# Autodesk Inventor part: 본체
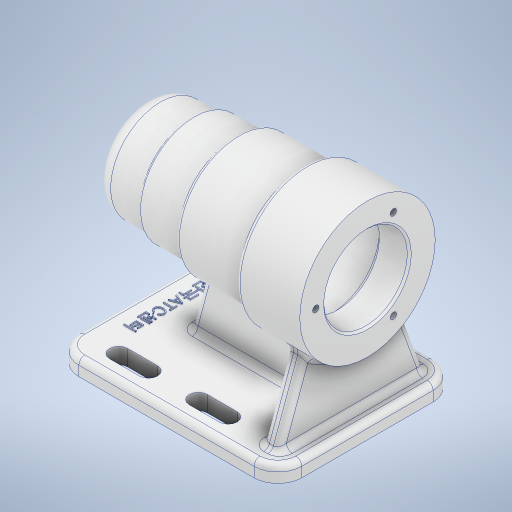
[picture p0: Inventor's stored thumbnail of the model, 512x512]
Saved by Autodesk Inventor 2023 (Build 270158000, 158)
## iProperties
Created: 2022-07
Part Number: 본체
Material: 알루미늄 6061
Document SubType Name: Modeling
Designer: owner
Density: 2.7 g/cm^3
Appearance: 알루미늄 - 평지
Author: owner
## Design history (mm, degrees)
sketch "스케치1"
  geometry: L1 (56, -45)-(-56, -45); L2 (-56, -45)-(-56, 45); L3 (-56, 45)-(56, 45); L4 (56, 45)-(56, -45); L5 (56, -45)-(-56, 45); L6 (-56, -45)-(56, 45); 1 further point
  constraints: 12 end point, 2 midpoint, 2 parallel, 1 horizontal, 1 perpendicular
  dimensions: "d0" = 112 distance of L1.start L1.end; "d1" = 90 distance of L1.end L2.end
extrude "돌출1" new body sketch "스케치1" distance "d2" = 8; taper "d3" = 0 deg
sketch "스케치2"
  geometry: L1 (-56, 70)-(56, 70); L2 (-56, 0)-(56, 0) reference; L3 (56, 0)-(56, 8) reference; L4 (-56, 70)-(-56, 87); L5 (-48, 95)-(-33, 95); L6 (-32, 96)-(-32, 96); L7 (-31, 97)-(-11.5, 97); L8 (-10, 98.5)-(-10, 98.5); L9 (-8.5, 100)-(22, 100); L10 (24, 102)-(24, 102); L11 (26, 104)-(56, 104); L12 (56, 104)-(56, 91); L13 (56, 91)-(41, 91); L14 (41, 91)-(41, 91); L15 (38, 94)-(-10, 94); L16 (-13, 91)-(-13, 91); L17 (-13, 91)-(-24.7, 91); L18 (-25, 90.7)-(-25, 87.5); L19 (-25, 87.5)-(-42.7, 87.5); L20 (-43, 87.2)-(-43, 86); L21 (-43, 86)-(-46.7, 86); L22 (-47, 85.7)-(-47, 80.5); L23 (-47, 80.5)-(-47, 80.5); L24 (-50, 77.5)-(-50, 70); A1 r 0.3 centre (-46.7, 85.7) between (-46.7, 86) and (-47, 85.7); A2 r 0.3 centre (-42.7, 87.2) between (-42.7, 87.5) and (-43, 87.2); A3 r 0.3 centre (-24.7, 90.7) between (-24.7, 91) and (-25, 90.7); A4 r 3 centre (-47, 77.5) between (-47, 80.5) and (-50, 77.5); A5 r 3 centre (-10, 91) between (-10, 94) and (-13, 91); A6 r 3 centre (38, 91) between (41, 91) and (38, 94); A7 r 8 centre (-48, 87) between (-48, 95) and (-56, 87); A8 r 1 centre (-31, 96) between (-31, 97) and (-32, 96); A9 r 1 centre (-33, 96) between (-33, 95) and (-32, 96); A10 r 1.5 centre (-8.5, 98.5) between (-8.5, 100) and (-10, 98.5); A11 r 1.5 centre (-11.5, 98.5) between (-11.5, 97) and (-10, 98.5); A12 r 2 centre (26, 102) between (26, 104) and (24, 102); A13 r 2 centre (22, 102) between (22, 100) and (24, 102); 12 further points
  constraints: 44 end point, 26 point on circle, 26 tangent, 20 perpendicular, 13 centre point, 10 point on line, 7 equal radius, 1 horizontal, 1 midpoint, 1 vertical
  dimensions: "d4" = 70 distance from line of point (0, 0) L1; "d5" = 112 distance of L1.start L1.end; "d6" = 21 diameter of L23 L1; "d7" = 50 diameter of L5 L1; "d8" = 32 diameter of L21 L1; "d9" = 35 diameter of L19 L1; "d10" = 42 diameter of L17 L1; "d11" = 48 diameter of L15 L1; "d12" = 42 diameter of L13 L1; "d13" = 54 diameter of L7 L1; "d14" = 60 diameter of L9 L1; "d15" = 68 diameter of L11 L1; "d16" = 24 distance between parallel lines of L6 L4; "d17" = 46 distance between parallel lines of L8 L4; "d18" = 80 distance between parallel lines of L4 L10; "d19" = 112 distance between parallel lines of L4 L12; "d20" = 15 distance between parallel lines of L12 L14; "d21" = 54 distance between parallel lines of L14 L16; "d22" = 12 distance of L16.end point (-25, 91); "d23" = 18 distance of L18.end point (-43, 87.5); "d24" = 4 distance of L20.end point (-47, 86); "d25" = 3 distance of L22.end point (-50, 80.5); "d26" = 0.3 radius of A1; "d27" = 3 radius of A4; "d28" = 8 radius of A7; "d29" = 1 radius of A8; "d30" = 1.5 radius of A10; "d31" = 2 radius of A12
revolve "회전1" sketch "스케치2" stored, may be unused: angle "d32" = 90 deg
chamfer "모따기1" distance "d33" = 1; stored, may be unused: second distance "d34" = 2, angle "d35" = 45 deg
sketch "스케치3"
  geometry: L1 (-36, 33)-(-21, 33); L2 (-36, 28.5)-(-21, 28.5); L3 (-21, 37.5)-(-36, 37.5); L4 (-56, 45)-(-56, -45) reference; L5 (4, 33)-(19, 33); L6 (4, 28.5)-(19, 28.5); L7 (19, 37.5)-(4, 37.5); L8 (-56, 0)-(0, 0); L9 (4, -28.5)-(19, -28.5); L10 (19, -37.5)-(4, -37.5); L11 (-36, -28.5)-(-21, -28.5); L12 (-21, -37.5)-(-36, -37.5); A1 r 4.5 centre (-36, 33) between (-36, 37.5) and (-36, 28.5); A2 r 4.5 centre (-21, 33) between (-21, 28.5) and (-21, 37.5); A3 r 4.5 centre (4, 33) between (4, 37.5) and (4, 28.5); A4 r 4.5 centre (19, 33) between (19, 28.5) and (19, 37.5); A5 r 4.5 centre (19, -33) between (19, -37.5) and (19, -28.5); A6 r 4.5 centre (4, -33) between (4, -28.5) and (4, -37.5); A7 r 4.5 centre (-21, -33) between (-21, -37.5) and (-21, -28.5); A8 r 4.5 centre (-36, -33) between (-36, -28.5) and (-36, -37.5); 2 further points
  constraints: 26 end point, 16 point on circle, 12 symmetric about line, 8 centre point, 8 tangent, 3 midpoint, 2 horizontal, 2 parallel, 2 point on line, 4 other
  dimensions: "d36" = 7.5 distance of point (-28.5, 33) L1.end; "d37" = 9 diameter of A2; "d38" = 20 distance from line of L4 L1.start; "d39" = 33 vertical distance of L8.end point (-28.5, 33); "d40" = 7.5 distance of point (11.5, 33) L5.end; "d41" = 9 diameter of A4; "d42" = 25 distance of L5.start L1.end
extrude "돌출2" cut sketch "스케치3" distance "d43" = 8; taper "d44" = 0 deg
node "작업 평면1"
sketch "스케치5"
  geometry: L1 (45.342, 23.409)-(8, 37); L2 (8, 37)-(8, -37); L3 (8, -37)-(45.342, -23.409); L4 (8, -45)-(8, 45) reference; A1 r 34 centre (70, 0) between (45.342, 23.409) and (45.342, -23.409) reference; 1 further point
  constraints: 6 end point, 2 point on circle, 1 collinear, 1 equal length, 1 vertical
  dimensions: "d46" = 74 distance of L1.end L2.end; "d47" = 110 deg angle of L4 L1; "d48" = 110 deg angle of L4 L3
extrude "돌출3" join sketch "스케치5" distance "d49" = 8; taper "d50" = 0 deg
sketch "스케치6"
  geometry: L1 (-19.622, 43)-(-29, 8); L2 (56, 8)-(-56, 8) reference; L3 (48, 8)-(48, 45.342) reference; L4 (-31, 43)-(-11.5, 43) reference; 1 further point
  constraints: 2 end point, 2 point on line
  dimensions: "d51" = 105 deg angle of L2 L1; "d52" = 77 distance from line of L3 L1.end
feature "리브1" sketch "스케치6" dims "d53" = 1, "d54" = 8, "d55" = 0, "d56" = 0, "d57" = 1, "d58" = 1
fillet "모깎기1" dims "d59" = 12
fillet "모깎기2" dims "d60" = 3
fillet "모깎기3" dims "d61" = 3
fillet "모깎기4" dims "d62" = 3
fillet "모깎기5" dims "d63" = 3
sketch "스케치7" dims "d71" = 52
  geometry: C1 r 10.5 at (0, 0) reference; 3 further points
  constraints: 2 horizontal alignment, 1 coincident, 2 other
hole "구멍1" sketch "스케치7" at (-26, 0) diameter "d64" = 3.242; stored, may be unused: countersink angle "d68" = 90 deg, drill point angle "d70" = 118 deg; dims "d65" = 8, "d66" = 4, "d67" = 2, "d69" = 11
sketch "스케치8"
  geometry: L1 (-56, 33)-(-56, -33) reference; L2 (44, 45)-(-44, 45) reference; 2 further points
  constraints: 1 horizontal alignment, 1 other
  dimensions: "d75" = 12 distance from line of L1 point (-44, 0)
feature "엠보싱1" sketch "스케치8" dims "d0" = 112, "d1" = 90, "d77" = 0.5, "d78" = 0
node "솔리드1"
pattern_circular "원형 패턴1" dims angle "d73" = 360 deg
feature "A9D066F2-1C7D-4E18-AEED-F7BC21143FA4" dims "d64" = 3.242, "d65" = 8, "d66" = 4, "d67" = 2, "d68" = 90 deg, "d69" = 11, "d70" = 118 deg
other parameters: "d45" = 48
